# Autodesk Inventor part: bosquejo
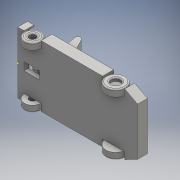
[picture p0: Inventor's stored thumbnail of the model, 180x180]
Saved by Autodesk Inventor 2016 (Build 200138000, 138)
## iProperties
Created: 2017-05
Part Number: bosquejo
Material: Generic
Document SubType Name: Modeling
Designer: laboratorioesan
Density: 1 g/cm^3
Appearance: Default
Author: laboratorioesan
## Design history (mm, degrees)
sketch "Sketch1"
  geometry: L1 (0, 0)-(-103.779, 0); L2 (-103.779, 0)-(-103.779, -29.217); L3 (-103.779, -29.217)-(-199.385, -29.217); L4 (-199.385, -29.217)-(-199.385, 0); L5 (-199.385, 0)-(-368.75, 0); L6 (-368.75, 0)-(-368.75, -29.217); L7 (-368.75, -29.217)-(-464.356, -29.217); L8 (-464.356, -29.217)-(-464.356, 0); L9 (-520.233, -29.217)-(-520.233, -237.101); L10 (-464.356, -266.318)-(-464.356, -237.101); L11 (-464.356, -237.101)-(-368.75, -237.101); L12 (-368.75, -237.101)-(-368.75, -266.318); L13 (-199.385, -266.318)-(-368.75, -266.318); L14 (-199.385, -266.318)-(-199.385, -237.101); L15 (-199.385, -237.101)-(-103.779, -237.101); L16 (-103.779, -237.101)-(-103.779, -266.318); L17 (-103.779, -266.318)-(0, -266.318); L18 (0, -266.318)-(0, 0); L19 (-464.356, -266.318)-(-520.233, -237.101); L20 (-464.356, 0)-(-520.233, -29.217)
  constraints: 40 end point, 10 perpendicular, 10 point on line, 6 horizontal alignment, 5 equal length, 1 horizontal, 1 vertical
extrude "Extrusion1" new body sketch "Sketch1" distance "d0" = 18; taper "d1" = 0 deg
sketch "Sketch4"
  geometry: L1 (0, 0)-(103.779, 0) reference; L2 (103.779, 0)-(103.779, 29.217) reference; L3 (103.779, 29.217)-(199.385, 29.217) reference; L4 (199.385, 29.217)-(199.385, 0) reference; L5 (199.385, 0)-(368.75, 0) reference; L6 (368.75, 0)-(368.75, 29.217) reference; L7 (368.75, 29.217)-(464.356, 29.217) reference; L8 (464.356, 29.217)-(464.356, 0) reference; L9 (464.356, 0)-(520.233, 29.217) reference; L10 (520.233, 29.217)-(520.233, 237.101) reference; L11 (520.233, 237.101)-(464.356, 266.318) reference; L12 (464.356, 266.318)-(464.356, 237.101) reference; L13 (464.356, 237.101)-(368.75, 237.101) reference; L14 (368.75, 237.101)-(368.75, 266.318) reference; L15 (368.75, 266.318)-(199.385, 266.318) reference; L16 (199.385, 266.318)-(199.385, 237.101) reference; L17 (199.385, 237.101)-(103.779, 237.101) reference; L18 (103.779, 237.101)-(103.779, 266.318) reference; L19 (103.779, 266.318)-(0, 266.318) reference; L20 (0, 266.318)-(0, 0) reference; L21 (6, 260.318)-(97.779, 260.318); L22 (97.779, 260.318)-(97.779, 237.101); L23 (205.385, 237.101)-(205.385, 260.318); L24 (205.385, 260.318)-(362.75, 260.318); L25 (362.75, 260.318)-(362.75, 237.101); L26 (464.356, 259.547)-(514.233, 233.467); L27 (514.233, 233.467)-(514.233, 32.851); L28 (514.233, 32.851)-(464.356, 6.771); L29 (362.75, 29.217)-(362.75, 6); L30 (362.75, 6)-(205.385, 6); L31 (205.385, 6)-(205.385, 29.217); L32 (97.779, 29.217)-(97.779, 6); L33 (97.779, 6)-(6, 6); L34 (6, 6)-(6, 260.318); L35 (103.779, 237.101)-(97.779, 237.101); L36 (199.385, 237.101)-(103.779, 237.101) reference; L37 (199.385, 237.101)-(205.385, 237.101); L38 (103.779, 0)-(103.779, 29.217) reference; L39 (103.779, 29.217)-(97.779, 29.217); L40 (199.385, 29.217)-(205.385, 29.217); L41 (368.75, 29.217)-(464.356, 29.217) reference; L42 (368.75, 29.217)-(362.75, 29.217); L43 (464.356, 237.101)-(368.75, 237.101) reference; L44 (368.75, 237.101)-(362.75, 237.101); 1 further point
  constraints: 40 end point, 5 point on line, 3 perpendicular, 1 other
  dimensions: "d5" = 6 distance between parallel lines of L19 L21
extrude "Extrusion3" join sketch "Sketch4" distance "d6" = 25; taper "d7" = 0 deg
sketch "Sketch5"
  geometry: L1 (0, 0)-(95.606, 0) reference; L2 (95.606, 0)-(95.606, 18) reference; L3 (0, 18)-(95.606, 18) reference; L4 (0, 0)-(0, 18) reference; L5 (264.971, 0)-(360.577, 0) reference; L6 (360.577, 0)-(360.577, 18) reference; L7 (264.971, 18)-(360.577, 18) reference; L8 (264.971, 0)-(264.971, 18) reference; L9 (95.606, 0)-(264.971, 0) reference; L10 (264.971, 0)-(264.971, 43) reference; L11 (95.606, 43)-(264.971, 43) reference; L12 (95.606, 0)-(95.606, 43) reference; L13 (-97.779, 18)-(-6, 18) reference; L14 (-103.779, 0)-(0, 0) reference; L15 (0, 0)-(0, 43) reference; L16 (-103.779, 43)-(0, 43) reference; L17 (-103.779, 0)-(-103.779, 43) reference; L18 (360.577, 0)-(416.454, 0) reference; L19 (416.454, 0)-(416.454, 43) reference; L20 (360.577, 43)-(416.454, 43) reference; L21 (360.577, 0)-(360.577, 43) reference; C1 r 42.5 at (47.803, 9); C2 r 42.5 at (312.774, 9); C3 r 20 at (47.803, 9); C4 r 20 at (312.774, 9); 3 further points
  constraints: 4 centre point, 2 coincident, 2 midpoint, 2 vertical alignment, 1 equal radius
  dimensions: "d8" = 85 diameter of C2; "d9" = 40 diameter of C3; "d10" = 40 diameter of C4
extrude "Extrusion4" join sketch "Sketch5" stored distance "d11" = 25; taper "d12" = 0 deg
sketch "Sketch6"
  geometry: L1 (0, 18)-(35.721, 18) reference; L2 (0, 0)-(35.721, 0) reference; L3 (264.971, 0)-(300.692, 0) reference; L4 (264.971, 18)-(300.692, 18) reference; A1 r 20 centre (17.861, 9) between (35.721, 0) and (35.721, 18) reference; A2 r 20 centre (17.861, 9) between (0, 18) and (0, 0) reference; A3 r 20 centre (282.832, 9) between (264.971, 18) and (264.971, 0) reference; A4 r 20 centre (282.832, 9) between (300.692, 0) and (300.692, 18) reference; A5 r 20 centre (17.861, 9) between (35.721, 0) and (35.721, 18) reference; A6 r 20 centre (282.832, 9) between (264.971, 18) and (264.971, 0) reference; 1 further point
extrude "Extrusion5" join sketch "Sketch6" distance "d14" = 15; taper "d15" = 0 deg
workplane "Work Plane1"
mirror "Mirror1"
mirror "Mirror2"
fillet "Fillet2" dims "d16" = 5
sketch "Sketch7"
  geometry: L1 (163.365, 0)-(6, 0) reference; L2 (163.365, 0)-(163.365, 25) reference; L3 (6, 25)-(163.365, 25) reference; L4 (6, 0)-(6, 25) reference; L5 (169.365, -18)-(0, -18) reference; L6 (0, -18)-(0, 25) reference; L7 (169.365, 25)-(0, 25) reference; L8 (169.365, -18)-(169.365, 25) reference; L9 (-43.536, 0)-(68.185, 96.214); L10 (68.185, 96.214)-(74.059, 89.394); L11 (74.059, 89.394)-(-29.744, 0); L12 (-43.536, 0)-(-29.744, 0); 1 further point
  constraints: 8 end point, 1 horizontal, 1 horizontal alignment, 1 parallel, 1 perpendicular
  dimensions: "d18" = 9 distance of L9.end L10.end
extrude "Extrusion6" join sketch "Sketch7" stored distance "d19" = 222; taper "d20" = 0 deg
sketch "Sketch8"
  geometry: L1 (0, 207.884)-(119.265, 207.884) reference; L2 (0, 0)-(0, 207.884) reference; L3 (119.265, 0)-(0, 0) reference; L4 (147.441, 0)-(119.265, 0) reference; L5 (147.441, 207.884)-(147.441, 0) reference; L6 (119.265, 207.884)-(147.441, 207.884) reference; L7 (0, 0)-(0, 207.884) reference; L8 (0, 0)-(119.265, 0); L9 (119.265, 0)-(119.265, 39.115); L10 (119.265, 39.115)-(0, 39.115); L11 (0, 39.115)-(0, 0); L12 (0, 207.884)-(119.265, 207.884); L13 (119.265, 207.884)-(119.265, 168.768); L14 (119.265, 168.768)-(0, 168.768); L15 (0, 168.768)-(0, 207.884); 1 further point
  constraints: 16 end point, 4 parallel, 2 horizontal, 2 perpendicular, 1 collinear, 1 point on line
extrude "Extrusion7" cut sketch "Sketch8" distance "d21" = 15; taper "d22" = 0 deg
fillet "Fillet3" dims "d23" = 10
sketch "Sketch9"
  geometry: L1 (0, -9)-(0, 0) reference; L2 (99.265, -9)-(0, -9) reference; L3 (99.265, 0)-(99.265, -9) reference; L4 (0, 0)-(99.265, 0) reference; L5 (0, 0)-(99.265, 0) reference; L6 (91.515, -9)-(10.062, -103.593); L7 (-21.682, -37.959)-(-16.933, -42.049) reference; L8 (-16.933, -42.049)-(-5.187, -28.41) reference; L9 (-9.936, -24.32)-(-5.187, -28.41) reference; L10 (118.6, -135.015)-(-0.641, -32.325) reference; L11 (-5.187, -28.41)-(-9.936, -24.32) reference; L12 (40.742, -67.964)-(-9.936, -24.32); L13 (-9.936, -24.32)-(3.258, -9); L14 (3.258, -9)-(91.515, -9); L15 (0, -9)-(99.265, -9) reference; A1 r 42.5 centre (-47.282, -4.035) between (-21.682, -37.959) and (-9.936, -24.32) reference; 1 further point
  constraints: 8 end point, 4 point on line, 1 collinear, 1 perpendicular
extrude "Extrusion8" join sketch "Sketch9" stored distance "d24" = 109.5; taper "d25" = 0 deg
workplane "Work Plane2"
sketch "Sketch10"
  geometry: L1 (75.222, 24.912)-(69.349, 18.092) reference; L2 (0.005, 89.688)-(75.222, 24.912) reference; L3 (-5.868, 82.869)-(0.005, 89.688) reference; L4 (0.005, 77.812)-(-5.868, 82.869) reference; L5 (0.005, 77.812)-(0, 0) reference; L6 (66.88, 0)-(0, 0) reference; L7 (66.88, 0)-(66.88, 20.218) reference; L8 (69.349, 18.092)-(66.88, 20.218) reference; L9 (0.005, 77.812)-(-5.868, 82.869) reference; L10 (69.349, 18.092)-(66.88, 20.218) reference; L11 (66.88, 20.218)-(0.005, 77.812); L12 (-5.868, 82.869)-(-13.445, 89.394) reference; 1 further point
  constraints: 2 end point, 1 collinear
extrude "Extrusion9" cut sketch "Sketch10" stored distance "d26" = 120; taper "d27" = 0 deg
sketch "Sketch12"
  geometry: L1 (199.385, 29.217)-(199.385, 0) reference; L2 (199.385, 0)-(368.75, 0) reference; L3 (368.75, 0)-(368.75, 29.217) reference; L4 (368.75, 29.217)-(362.75, 29.217) reference; L5 (362.75, 29.217)-(362.75, 6) reference; L6 (362.75, 6)-(205.385, 6) reference; L7 (205.385, 6)-(205.385, 29.217) reference; L8 (205.385, 29.217)-(199.385, 29.217) reference; L9 (368.75, 237.101)-(368.75, 266.318) reference; L10 (368.75, 266.318)-(199.385, 266.318) reference; L11 (199.385, 266.318)-(199.385, 237.101) reference; L12 (199.385, 237.101)-(205.385, 237.101) reference; L13 (205.385, 237.101)-(205.385, 260.318) reference; L14 (205.385, 260.318)-(362.75, 260.318) reference; L15 (362.75, 260.318)-(362.75, 237.101) reference; L16 (362.75, 237.101)-(368.75, 237.101) reference; L17 (368.75, 237.101)-(368.75, 266.318) reference; L18 (368.75, 237.101)-(199.385, 237.101); L19 (199.385, 237.101)-(199.385, 266.318); L20 (199.385, 266.318)-(368.75, 266.318); L21 (368.75, 266.318)-(368.75, 237.101); L22 (199.385, 0)-(368.75, 0) reference; L23 (368.75, 29.217)-(199.385, 29.217); L24 (199.385, 29.217)-(199.385, 0); L25 (199.385, 0)-(368.75, 0); L26 (368.75, 0)-(368.75, 29.217); 1 further point
  constraints: 16 end point, 4 parallel, 2 horizontal, 2 perpendicular
extrude "Extrusion11" join sketch "Sketch12" distance "d30" = 5; taper "d31" = 0 deg
sketch "Sketch13"
  geometry: L1 (0, 0)-(169.365, 0) reference; L2 (169.365, 0)-(169.365, 48) reference; L3 (0, 48)-(169.365, 48) reference; L4 (0, 0)-(0, 48) reference; L5 (-199.385, 0)-(-95.606, 0) reference; L6 (-95.606, 0)-(-95.606, 43) reference; L7 (-199.385, 43)-(-95.606, 43) reference; L8 (-199.385, 0)-(-199.385, 43) reference; L9 (-95.606, 64.067)-(0, 64.067); L10 (0, 64.067)-(0, -46.915); L11 (0, -46.915)-(-95.606, -46.915); L12 (-95.606, -46.915)-(-95.606, 64.067); 1 further point
  constraints: 8 end point, 2 parallel, 1 horizontal, 1 perpendicular
extrude "Extrusion12" cut sketch "Sketch13" distance "d32" = 293; taper "d33" = 0 deg
sketch "Sketch14"
  geometry: L1 (6, 0)-(0, 0) reference; L2 (6, 0)-(6, 25) reference; L3 (0, 25)-(6, 25) reference; L4 (0, 0)-(0, 25) reference; L5 (6, 0)-(6, 25) reference; L6 (0, 25)-(6, 25); L7 (6, 25)-(6, 0); L8 (6, 0)-(0, 0); L9 (0, 0)-(0, 25); 1 further point
  constraints: 8 end point, 2 parallel, 1 horizontal, 1 perpendicular
extrude "Extrusion13" cut sketch "Sketch14" stored distance "d34" = 600; taper "d35" = 0 deg
sketch "Sketch15"
  geometry: L1 (0, 0)-(0, 25) reference; L2 (6, 0)-(0, 0) reference; L3 (6, 0)-(6, 30) reference; L4 (-163.365, 30)-(6, 30) reference; L5 (-163.365, 0)-(-163.365, 30) reference; L6 (-157.365, 0)-(-163.365, 0) reference; L7 (-157.365, 0)-(-157.365, 25) reference; L8 (-157.365, 25)-(0, 25) reference; L9 (-163.365, 30)-(-157.365, 30); L10 (-157.365, 30)-(-157.365, 0); L11 (-157.365, 0)-(-163.365, 0); L12 (-163.365, 0)-(-163.365, 30); 1 further point
  constraints: 8 end point, 2 parallel, 1 horizontal, 1 perpendicular
extrude "Extrusion14" cut sketch "Sketch15" stored distance "d36" = 600; taper "d37" = 0 deg
sketch "Sketch16"
  geometry: L1 (266.318, 18)-(0, 18) reference; L2 (0, 0)-(0, 18) reference; L3 (0, 0)-(266.318, 0) reference; L4 (266.318, 0)-(266.318, 18) reference; L5 (6, 18)-(6, 43) reference; L6 (0, 43)-(6, 43) reference; L7 (0, 18)-(0, 43) reference; L8 (6, 18)-(0, 18) reference; L9 (260.318, 18)-(260.318, 43) reference; L10 (266.318, 18)-(260.318, 18) reference; L11 (266.318, 43)-(266.318, 18) reference; L12 (260.318, 43)-(266.318, 43) reference; 1 further point
extrude "Extrusion15" join sketch "Sketch16" stored distance "d38" = 205; taper "d39" = 0 deg
sketch "Sketch17"
  geometry: L1 (375.017, 193.159)-(308.137, 193.159) reference; L2 (308.137, 193.159)-(308.137, 197.986) reference; L3 (308.137, 197.986)-(375.017, 197.986) reference; L4 (375.017, 197.986)-(375.017, 193.159) reference; L5 (375.017, 73.159)-(375.017, 68.332) reference; L6 (375.017, 68.332)-(308.137, 68.332) reference; L7 (308.137, 68.332)-(308.137, 73.159) reference; L8 (308.137, 73.159)-(375.017, 73.159) reference; L9 (362.75, 260.318)-(6, 260.318) reference; L10 (6, 260.318)-(6, 6) reference; L11 (6, 6)-(362.75, 6) reference; L12 (362.75, 6)-(362.75, 29.217) reference; L13 (362.75, 29.217)-(368.75, 29.217) reference; L14 (368.75, 29.217)-(375.017, 29.217) reference; L15 (375.017, 29.217)-(375.017, 24.217) reference; L16 (380.149, 29.217)-(398.494, 29.217) reference; L17 (398.494, 29.217)-(398.494, 237.101) reference; L18 (398.494, 237.101)-(380.149, 237.101) reference; L19 (375.017, 242.101)-(375.017, 237.101) reference; L20 (375.017, 237.101)-(368.75, 237.101) reference; L21 (368.75, 237.101)-(362.75, 237.101) reference; L22 (362.75, 237.101)-(362.75, 260.318) reference; L23 (205.385, 237.101)-(362.75, 237.101) reference; L24 (362.75, 260.318)-(101.399, 260.318); L25 (101.399, 260.318)-(101.399, 237.101); L26 (101.399, 237.101)-(362.75, 237.101); L27 (362.75, 237.101)-(362.75, 260.318); L28 (362.75, 260.318)-(362.75, 237.101) reference; L29 (205.385, 266.318)-(0, 266.318) reference; L30 (362.75, 237.101)-(101.399, 237.101); L31 (101.399, 237.101)-(101.399, 266.318); L32 (101.399, 266.318)-(362.75, 266.318); L33 (362.75, 266.318)-(362.75, 237.101); 1 further point
  constraints: 16 end point, 4 parallel, 2 horizontal, 2 perpendicular, 2 point on line, 2 other
extrude "Extrusion16" join sketch "Sketch17" distance "d40" = 30; taper "d41" = 0 deg
sketch "Sketch18"
  geometry: L1 (205.385, 29.217)-(205.385, 0) reference; L2 (205.385, 0)-(368.75, 0) reference; L3 (368.75, 0)-(368.75, 29.217) reference; L4 (368.75, 29.217)-(205.385, 29.217) reference; L5 (101.399, 237.101)-(368.75, 237.101) reference; L6 (368.75, 237.101)-(368.75, 266.318) reference; L7 (368.75, 266.318)-(101.399, 266.318) reference; L8 (101.399, 266.318)-(101.399, 237.101) reference; L9 (0, 0)-(368.75, 0) reference; L10 (368.75, 29.217)-(101.399, 29.217); L11 (101.399, 29.217)-(101.399, 0); L12 (101.399, 0)-(368.75, 0); L13 (368.75, 0)-(368.75, 29.217)
  constraints: 8 end point, 2 parallel, 1 horizontal, 1 perpendicular, 1 point on line
extrude "Extrusion17" join sketch "Sketch18" distance "d42" = 30; taper "d43" = 0 deg
sketch "Sketch19"
  geometry: L1 (267.352, 18)-(267.352, 48) reference; L2 (0, 48)-(267.352, 48) reference; L3 (0, 0)-(0, 48) reference; L4 (0, 0)-(368.75, 0) reference; L5 (368.75, 0)-(368.75, 43) reference; L6 (267.352, 43)-(368.75, 43) reference; L7 (267.352, 43)-(267.352, 48) reference; L8 (368.75, 0)-(0, 0) reference; L9 (267.352, 43)-(340.912, 43); L10 (340.912, 43)-(340.912, 0); L11 (340.912, 0)-(267.352, 0); L12 (267.352, 0)-(267.352, 43)
  constraints: 8 end point, 2 parallel, 1 horizontal, 1 perpendicular, 1 point on line
extrude "Extrusion18" cut sketch "Sketch19" stored distance "d44" = 60; taper "d45" = 0 deg
sketch "Sketch20"
  geometry: L1 (0, 43)-(101.399, 43) reference; L2 (0, 0)-(0, 43) reference; L3 (0, 0)-(368.75, 0) reference; L4 (368.75, 0)-(368.75, 48) reference; L5 (101.399, 48)-(368.75, 48) reference; L6 (101.399, 43)-(101.399, 48) reference; L7 (27.838, 18)-(27.838, 43) reference; L8 (0, 43)-(101.399, 43) reference; L9 (101.399, 43)-(27.838, 43); L10 (27.838, 43)-(27.838, 0); L11 (27.838, 0)-(101.399, 0); L12 (101.399, 0)-(101.399, 43); L13 (27.838, 43)-(101.399, 43); L14 (101.399, 43)-(101.399, 0); L15 (101.399, 0)-(27.838, 0); L16 (27.838, 0)-(27.838, 43); L17 (27.838, 43)-(101.399, 43); L18 (101.399, 43)-(101.399, 0); L19 (101.399, 0)-(27.838, 0); L20 (27.838, 0)-(27.838, 43); 1 further point
  constraints: 24 end point, 6 parallel, 3 horizontal, 3 perpendicular, 1 point on line
extrude "Extrusion19" cut sketch "Sketch20" distance "d46" = 30; taper "d47" = 0 deg
sketch "Sketch21"
  geometry: L1 (27.838, 18)-(101.399, 18) reference; L2 (27.838, 0)-(27.838, 18) reference; L3 (101.399, 0)-(27.838, 0) reference; L4 (101.399, 18)-(101.399, 0) reference; C1 r 35.481 at (64.618, 0); C2 r 14.208 at (64.618, 0); 1 further point
  constraints: 2 centre point, 1 coincident, 1 midpoint
extrude "Extrusion20" join sketch "Sketch21" distance "d48" = 30; taper "d49" = 0 deg
fillet "Fillet4" dims "d50" = 7
sketch "Sketch22"
  geometry: L1 (375.017, 73.159)-(375.017, 68.332) reference; L2 (375.017, 68.332)-(308.137, 68.332) reference; L3 (308.137, 68.332)-(308.137, 73.159) reference; L4 (308.137, 73.159)-(375.017, 73.159) reference; L5 (375.017, 193.159)-(308.137, 193.159) reference; L6 (308.137, 193.159)-(308.137, 197.986) reference; L7 (308.137, 197.986)-(375.017, 197.986) reference; L8 (375.017, 197.986)-(375.017, 193.159) reference; L9 (27.838, 6)-(27.838, 30) reference; L10 (27.838, 30)-(34.043, 30) reference; L11 (34.043, 30)-(95.194, 30) reference; L12 (95.194, 30)-(101.399, 30) reference; L13 (101.399, 30)-(101.399, 29.217) reference; L14 (101.399, 29.217)-(368.75, 29.217) reference; L15 (368.75, 29.217)-(375.017, 29.217) reference; L16 (375.017, 29.217)-(375.017, 24.217) reference; L17 (380.149, 29.217)-(398.494, 29.217) reference; L18 (398.494, 29.217)-(398.494, 237.101) reference; L19 (398.494, 237.101)-(380.149, 237.101) reference; L20 (375.017, 242.101)-(375.017, 237.101) reference; L21 (375.017, 237.101)-(368.75, 237.101) reference; L22 (368.75, 237.101)-(101.399, 237.101) reference; L23 (101.399, 237.101)-(101.399, 236.318) reference; L24 (101.399, 236.318)-(27.838, 236.318) reference; L25 (27.838, 236.318)-(27.838, 260.318) reference; L26 (27.838, 260.318)-(6, 260.318) reference; L27 (6, 260.318)-(6, 6) reference; L28 (6, 6)-(27.838, 6) reference; L29 (141.173, 217.361)-(272.262, 217.361); L30 (272.262, 217.361)-(272.262, 43.696); L31 (272.262, 43.696)-(141.173, 43.696); L32 (141.173, 43.696)-(141.173, 217.361); 1 further point
  constraints: 8 end point, 2 parallel, 1 horizontal, 1 perpendicular, 2 other
extrude "Extrusion21" join sketch "Sketch22" distance "d51" = 9; taper "d52" = 0 deg
sketch "Sketch23"
  geometry: L1 (0, 0)-(131.089, 0) reference; L2 (0, 0)-(0, 9) reference; L3 (131.089, 9)-(0, 9) reference; L4 (131.089, 0)-(131.089, 9) reference; L5 (0, 9)-(-25.482, 124.633); L6 (-25.482, 124.633)-(-3.264, 124.633); L7 (-3.264, 124.633)-(27.617, 62.873); L8 (27.617, 62.873)-(27.617, 9); L9 (131.089, 9)-(0, 9) reference; 1 further point
  constraints: 8 end point, 1 horizontal, 1 perpendicular, 1 point on line
extrude "Extrusion22" join sketch "Sketch23" stored distance "d53" = 9; taper "d54" = 0 deg
fillet "Fillet5" dims "d55" = 80
fillet "Fillet6" dims "d56" = 20
workplane "Work Plane3"
mirror "Mirror3"
fillet "Fillet7" dims "d57" = 7
sketch "Sketch24"
  geometry: L1 (272.262, 217.361)-(272.262, 43.696) reference; L2 (272.262, 43.696)-(141.173, 43.696) reference; L3 (141.173, 43.696)-(141.173, 217.361) reference; L4 (141.173, 217.361)-(272.262, 217.361) reference; L5 (375.017, 73.159)-(375.017, 68.332) reference; L6 (375.017, 68.332)-(308.137, 68.332) reference; L7 (308.137, 68.332)-(308.137, 73.159) reference; L8 (308.137, 73.159)-(375.017, 73.159) reference; L9 (375.017, 193.159)-(308.137, 193.159) reference; L10 (308.137, 193.159)-(308.137, 197.986) reference; L11 (308.137, 197.986)-(375.017, 197.986) reference; L12 (375.017, 197.986)-(375.017, 193.159) reference; L13 (27.838, 6)-(27.838, 30) reference; L14 (27.838, 30)-(34.043, 30) reference; L15 (34.043, 30)-(95.194, 30) reference; L16 (95.194, 30)-(101.399, 30) reference; L17 (101.399, 30)-(101.399, 29.217) reference; L18 (101.399, 29.217)-(368.75, 29.217) reference; L19 (368.75, 29.217)-(375.017, 29.217) reference; L20 (375.017, 29.217)-(375.017, 24.217) reference; L21 (380.149, 29.217)-(398.494, 29.217) reference; L22 (398.494, 29.217)-(398.494, 237.101) reference; L23 (398.494, 237.101)-(380.149, 237.101) reference; L24 (375.017, 242.101)-(375.017, 237.101) reference; L25 (375.017, 237.101)-(368.75, 237.101) reference; L26 (368.75, 237.101)-(101.399, 237.101) reference; L27 (101.399, 237.101)-(101.399, 236.318) reference; L28 (101.399, 236.318)-(95.194, 236.318) reference; L29 (95.194, 236.318)-(95.194, 243.318) reference; L30 (86.69, 236.318)-(42.547, 236.318) reference; L31 (34.043, 243.318)-(34.043, 236.318) reference; L32 (34.043, 236.318)-(27.838, 236.318) reference; L33 (27.838, 236.318)-(27.838, 260.318) reference; L34 (27.838, 260.318)-(6, 260.318) reference; L35 (6, 260.318)-(6, 6) reference; L36 (6, 6)-(27.838, 6) reference; L37 (95.194, 150.026)-(27.838, 150.026); L38 (27.838, 150.026)-(27.838, 115.95); L39 (27.838, 115.95)-(95.194, 115.95); L40 (95.194, 115.95)-(95.194, 150.026); 1 further point
  constraints: 8 end point, 2 parallel, 1 horizontal, 1 perpendicular, 4 other
extrude "Extrusion23" cut sketch "Sketch24" distance "d58" = 20; taper "d59" = 0 deg
sketch "Sketch25"
  geometry: L1 (-34.043, 18)-(-95.194, 18) reference; C1 r 4.394 at (-64.618, 28.481); A1 r 35.481 centre (-64.618, 0) between (-34.043, 18) and (-95.194, 18) reference; 2 further points
  constraints: 1 centre point, 1 vertical alignment, 1 other
extrude "Extrusion24" join sketch "Sketch25" distance "d60" = 210; taper "d61" = 0 deg
workplane "Work Plane4"
sketch "Sketch26"
  geometry: 1 further point
sketch "Sketch27"
  geometry: L1 (-119.827, 123.862)-(-141.173, 27) reference; L2 (-141.173, 27)-(-141.173, 18) reference; L3 (-141.173, 18)-(-95.194, 18) reference; L4 (-95.194, 18)-(-95.194, 0) reference; L5 (-95.194, 0)-(-520.233, 0) reference; L6 (-520.233, 0)-(-520.233, 43) reference; L7 (-520.233, 43)-(-514.233, 43) reference; L8 (-514.233, 43)-(-514.233, 18) reference; L9 (-514.233, 18)-(-412.286, 18) reference; L10 (-412.286, 18)-(-300.565, 114.214) reference; L11 (-300.565, 114.214)-(-294.692, 107.394) reference; L12 (-294.692, 107.394)-(-398.494, 18) reference; L13 (-398.494, 18)-(-272.262, 18) reference; L14 (-272.262, 18)-(-272.262, 27) reference; L15 (-272.262, 27)-(-244.402, 27) reference; L16 (-166.847, 84.757)-(-143.437, 131.577) reference; L17 (-6, 43)-(0, 43) reference; L18 (0, 43)-(0, 0) reference; L19 (0, 0)-(-27.838, 0) reference; L20 (-27.838, 0)-(-27.838, 18) reference; L21 (-27.838, 18)-(-6, 18) reference; L22 (-6, 18)-(-6, 43) reference; C1 r 4.394 at (-64.618, 28.481) reference; C2 r 20.48 at (-64.618, 28.481); A1 r 20 centre (-139.358, 128.166) between (-119.827, 123.862) and (-125.548, 142.633) reference; A2 r 80 centre (-244.402, 107) between (-244.402, 27) and (-169.848, 77.99) reference; A3 r 80 centre (-95.293, 48.98) between (-166.847, 84.757) and (-169.848, 77.99) reference; A4 r 20 centre (-125.548, 122.633) between (-125.548, 142.633) and (-143.437, 131.577) reference
  constraints: 1 centre point, 1 coincident
extrude "Extrusion25" join sketch "Sketch27" stored distance "d63" = 10; taper "d64" = 0 deg
body "Solid1"
node "Projected Loop3"
node "Projected Loop4"
node "Projected Loop5"
node "Projected Loop6"
node "Projected Loop7"
node "Projected Loop8"
node "Projected Loop9"
node "Projected Loop10"
node "Projected Loop11"
node "Projected Loop12"
node "Projected Loop13"
node "Projected Loop14"
node "Projected Loop15"
node "Projected Loop16"
node "Projected Loop22"
node "Projected Loop23"
node "Projected Loop24"
node "Projected Loop25"
node "Projected Loop26"
node "Projected Loop27"
node "Projected Loop28"
node "Projected Loop29"
node "Projected Loop30"
node "Projected Loop31"
node "Projected Loop32"
node "Projected Loop33"
node "Projected Loop34"
node "Projected Loop35"
node "Projected Loop36"
node "Projected Loop37"
node "Projected Loop38"
node "Projected Loop39"
node "Projected Loop40"
node "Project Cut Edges1"
other parameters: "d62" = 105
